// Mitsubishi GX Works2 project: Vol2_R_Cutter_PLC   PLC: Q06UDEH

PROGRAM MAIN
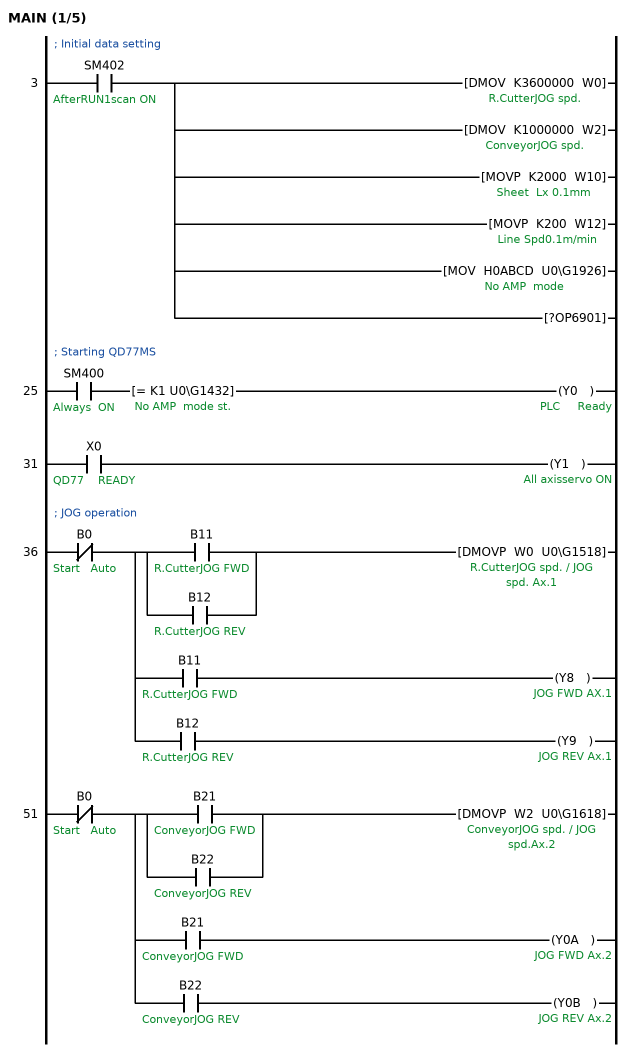
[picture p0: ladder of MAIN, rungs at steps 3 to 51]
; 
; Initial data setting
; 
3     LD      SM402  ; AfterRUN1scan ON
      DMOV    K3600000 W0  ; R.CutterJOG spd.
        [note] JOG speed set : x0.001deg/min
      DMOV    K1000000 W2  ; ConveyorJOG spd.
        [note] JOG speed set : x0.01mm/min
      MOVP    K2000 W10  ; Sheet  Lx 0.1mm
        [note] Production setting
      MOVP    K200 W12  ; Line Spd0.1m/min
      MOV     H0ABCD U0\G1926  ; No AMP  mode
      ?OP6901
; 
; Starting QD77MS
; 
25    LD      SM400  ; Always  ON
      AND=    K1 U0\G1432  ; No AMP  mode st.
      OUT     Y0  ; PLC     Ready
31    LD      X0  ; QD77    READY
      OUT     Y1  ; All axisservo ON
; 
; JOG operation
; 
36    LDI     B0  ; Start   Auto
      MPS
      LD      B11  ; R.CutterJOG FWD
      OR      B12  ; R.CutterJOG REV
      ANB
      DMOVP   W0 U0\G1518  ; JOG spd. Ax.1
      MRD
      AND     B11  ; R.CutterJOG FWD
      OUT     Y8  ; JOG FWD AX.1
      MPP
      AND     B12  ; R.CutterJOG REV
      OUT     Y9  ; JOG REV Ax.1
51    LDI     B0  ; Start   Auto
      MPS
      LD      B21  ; ConveyorJOG FWD
      OR      B22  ; ConveyorJOG REV
      ANB
      DMOVP   W2 U0\G1618  ; JOG spd.Ax.2
      MRD
      AND     B21  ; ConveyorJOG FWD
      OUT     Y0A  ; JOG FWD Ax.2
      MPP
      AND     B22  ; ConveyorJOG REV
      OUT     Y0B  ; JOG REV Ax.2
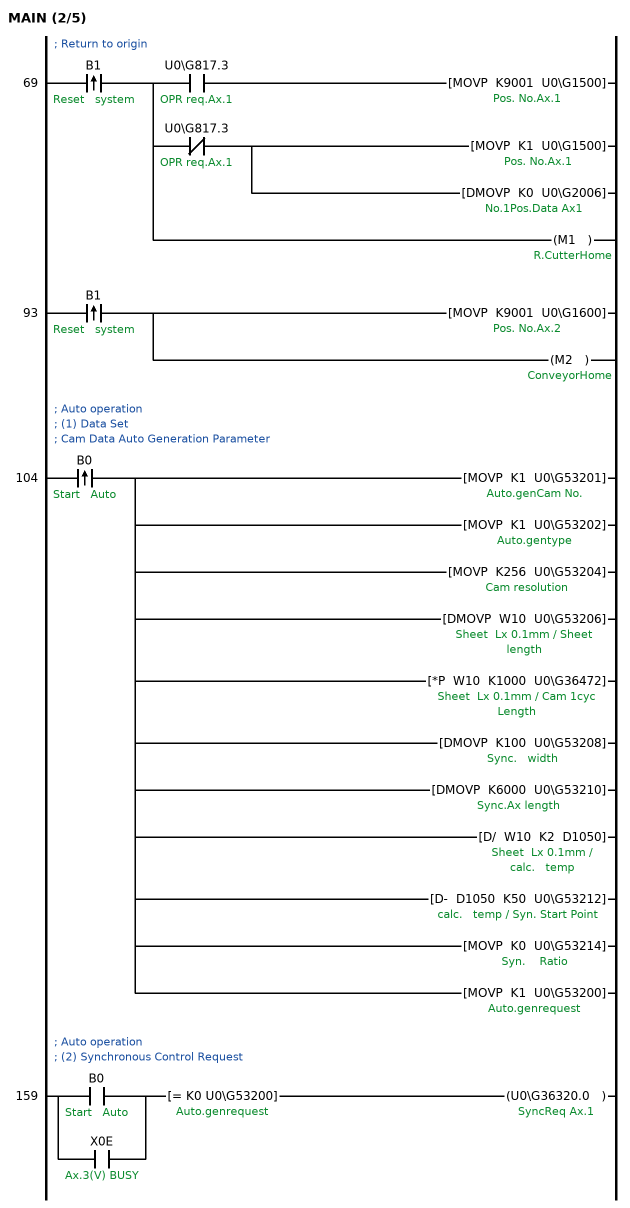
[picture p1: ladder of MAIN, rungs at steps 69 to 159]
; 
; Return to origin
; 
69    LDP     B1  ; Reset   system
      MPS
      AND     U0\G817.3  ; OPR req.Ax.1
      MOVP    K9001 U0\G1500  ; Pos. No.Ax.1
      MRD
      ANI     U0\G817.3  ; OPR req.Ax.1
      MOVP    K1 U0\G1500
      DMOVP   K0 U0\G2006  ; No.1Pos.Data Ax1
      MPP
      OUT     M1  ; R.CutterHome
93    LDP     B1  ; Reset   system
      MOVP    K9001 U0\G1600  ; Pos. No.Ax.2
      OUT     M2  ; ConveyorHome
; 
; Auto operation
; (1) Data Set
; Cam Data Auto Generation Parameter
; 
104   LDP     B0  ; Start   Auto
      MOVP    K1 U0\G53201  ; Auto.genCam No.
        [note] Cam auto-generation parameter.
      MOVP    K1 U0\G53202  ; Auto.gentype
      MOVP    K256 U0\G53204  ; Cam resolution
      DMOVP   W10 U0\G53206  ; Sheet   length
      *P      W10 K1000 U0\G36472  ; Cam 1cyc Length
      DMOVP   K100 U0\G53208  ; Sync.   width
      DMOVP   K6000 U0\G53210  ; Sync.Ax length
      D/      W10 K2 D1050  ; calc.   temp
      D-      D1050 K50 U0\G53212  ; Syn. Start Point
      MOVP    K0 U0\G53214  ; Syn.    Ratio
      MOVP    K1 U0\G53200  ; Auto.genrequest
; 
; Auto operation
; (2) Synchronous Control Request
; 
159   LD      B0  ; Start   Auto
      OR      X0E  ; Ax.3(V) BUSY
      AND=    K0 U0\G53200  ; Auto.genrequest
      OUT     U0\G36320.0  ; SyncReq Ax.1
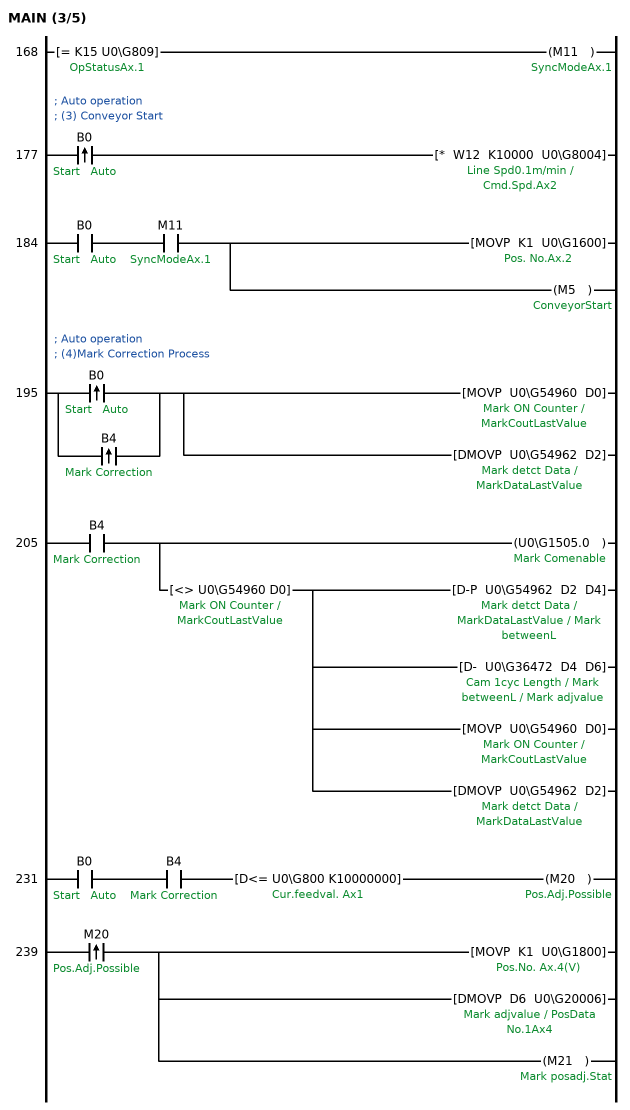
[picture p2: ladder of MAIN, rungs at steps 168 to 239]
168   LD=     K15 U0\G809  ; OpStatusAx.1
      OUT     M11  ; SyncModeAx.1
; 
; Auto operation
; (3) Conveyor Start
; 
177   LDP     B0  ; Start   Auto
      *       W12 K10000 U0\G8004  ; Cmd.Spd.Ax2
        [note] Conveyor Speed Set
184   LD      B0  ; Start   Auto
      AND     M11  ; SyncModeAx.1
      MOVP    K1 U0\G1600
      OUT     M5  ; ConveyorStart
; 
; Auto operation
; (4)Mark Correction Process
; 
195   LDP     B0  ; Start   Auto
      ORP     B4  ; Mark Correction
      MOVP    U0\G54960 D0  ; Mark ON Counter / MarkCoutLastValue
      DMOVP   U0\G54962 D2  ; Mark detct Data / MarkDataLastValue
205   LD      B4  ; Mark Correction
      OUT     U0\G1505.0  ; Mark Comenable
      AND<>   U0\G54960 D0  ; Mark ON Counter / MarkCoutLastValue
      D-P     U0\G54962 D2 D4  ; Mark    betweenL
      D-      U0\G36472 D4 D6  ; Mark adjvalue
      MOVP    U0\G54960 D0
      DMOVP   U0\G54962 D2
231   LD      B0  ; Start   Auto
      AND     B4  ; Mark Correction
      ANDD<=  U0\G800 K10000000  ; Cur.feedval. Ax1
      OUT     M20  ; Pos.Adj.Possible
239   LDP     M20  ; Pos.Adj.Possible
      MOVP    K1 U0\G1800  ; Pos.No. Ax.4(V)
      DMOVP   D6 U0\G20006  ; PosData No.1Ax4
      OUT     M21  ; Mark posadj.Stat
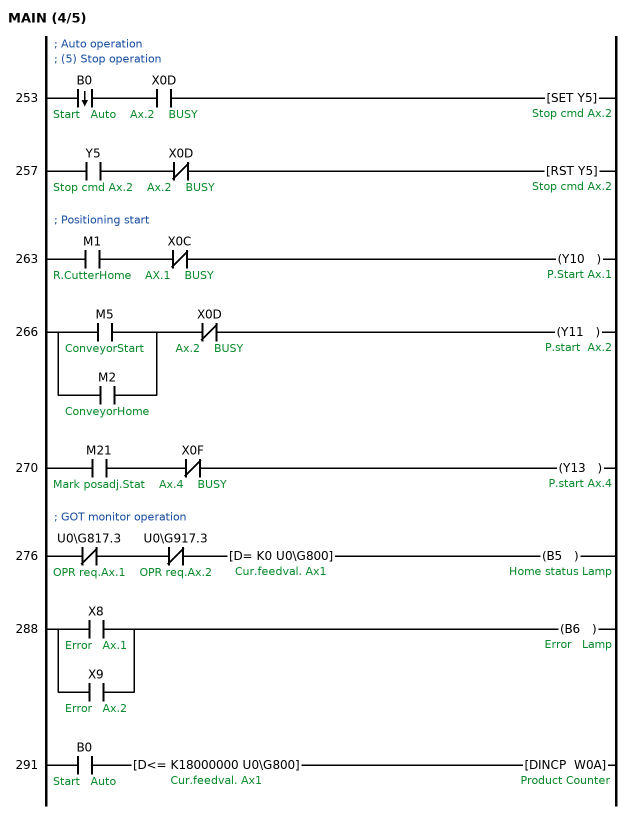
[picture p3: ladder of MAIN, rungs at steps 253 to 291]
; 
; Auto operation
; (5) Stop operation
; 
253   LDF     B0  ; Start   Auto
      AND     X0D  ; Ax.2    BUSY
      SET     Y5  ; Stop cmd Ax.2
        [note] Axes Stop Command
257   LD      Y5  ; Stop cmd Ax.2
      ANI     X0D  ; Ax.2    BUSY
      RST     Y5  ; Stop cmd Ax.2
; 
; Positioning start
; 
263   LD      M1  ; R.CutterHome
      ANI     X0C  ; AX.1    BUSY
      OUT     Y10  ; P.Start Ax.1
266   LD      M5  ; ConveyorStart
      OR      M2  ; ConveyorHome
      ANI     X0D  ; Ax.2    BUSY
      OUT     Y11  ; P.start  Ax.2
270   LD      M21  ; Mark posadj.Stat
      ANI     X0F  ; Ax.4    BUSY
      OUT     Y13  ; P.start Ax.4
; 
; GOT monitor operation
; 
276   LDI     U0\G817.3  ; OPR req.Ax.1
      ANI     U0\G917.3  ; OPR req.Ax.2
      ANDD=   K0 U0\G800  ; Cur.feedval. Ax1
      OUT     B5  ; Home status Lamp
288   LD      X8  ; Error   Ax.1
      OR      X9  ; Error   Ax.2
      OUT     B6  ; Error   Lamp
291   LD      B0  ; Start   Auto
      ANDD<=  K18000000 U0\G800  ; Cur.feedval. Ax1
      DINCP   W0A  ; Product Counter
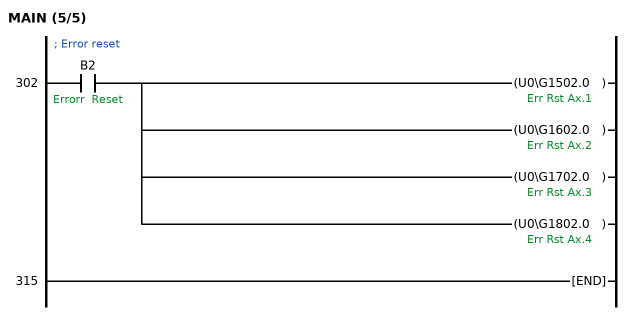
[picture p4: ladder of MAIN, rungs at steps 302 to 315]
; 
; Error reset
; 
302   LD      B2  ; Errorr  Reset
      OUT     U0\G1502.0  ; Err Rst Ax.1
      OUT     U0\G1602.0  ; Err Rst Ax.2
      OUT     U0\G1702.0  ; Err Rst Ax.3
      OUT     U0\G1802.0  ; Err Rst Ax.4
315   END
END_PROGRAM

PROGRAM Mark_Sim
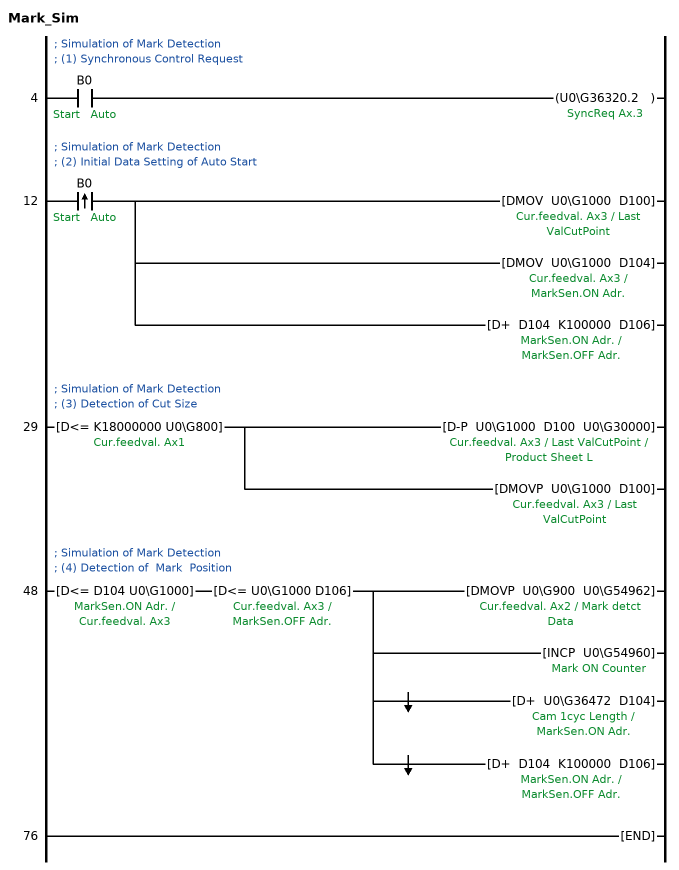
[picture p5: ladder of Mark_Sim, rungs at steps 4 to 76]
; 
; Simulation of Mark Detection
; (1) Synchronous Control Request
; 
4     LD      B0  ; Start   Auto
      OUT     U0\G36320.2  ; SyncReq Ax.3
; 
; Simulation of Mark Detection
; (2) Initial Data Setting of Auto Start
; 
12    LDP     B0  ; Start   Auto
      DMOV    U0\G1000 D100  ; Cur.feedval. Ax3 / Last ValCutPoint
      DMOV    U0\G1000 D104  ; MarkSen.ON Adr.
      D+      D104 K100000 D106  ; MarkSen.OFF Adr.
; 
; Simulation of Mark Detection
; (3) Detection of Cut Size
; 
29    LDD<=   K18000000 U0\G800  ; Cur.feedval. Ax1
      D-P     U0\G1000 D100 U0\G30000  ; Product Sheet L
      DMOVP   U0\G1000 D100
; 
; Simulation of Mark Detection
; (4) Detection of  Mark  Position
; 
48    LDD<=   D104 U0\G1000  ; MarkSen.ON Adr. / Cur.feedval. Ax3
      ANDD<=  U0\G1000 D106  ; Cur.feedval. Ax3 / MarkSen.OFF Adr.
      DMOVP   U0\G900 U0\G54962  ; Cur.feedval. Ax2 / Mark detct Data
      INCP    U0\G54960  ; Mark ON Counter
      MPS
      MEF
      D+      U0\G36472 D104  ; Cam 1cyc Length
      MPP
      MEF
      D+      D104 K100000 D106
76    END
END_PROGRAM

// device comments not shown above
Y6  ; Stop cmdAx.3(V)
Y12  ; P.start Ax.3(V)
Y14  ; P.start Ax.5
Y15  ; Axis 6Positioning start
Y16  ; Axis 7Positioning start
Y17  ; Axis 8Positioning start
Y18  ; P.start Ax.9(V)
Y19  ; P.start Ax.10(V)
Y1A  ; Axis11Positioning start
Y1B  ; Axis12Positioning start
Y1C  ; Axis13Positioning start
Y1D  ; Axis14Positioning start
Y1E  ; Axis15Positioning start
Y1F  ; Axis16Positioning start
Y20  ; Mark ON
X1  ; Synchronization flag
X10  ; Axis 1  BUSY
X11  ; Axis 2  BUSY
X12  ; Axis 3  BUSY
X13  ; Axis 4  BUSY
X14  ; Axis 5  BUSY
X15  ; Axis 6  BUSY
X16  ; Axis 7  BUSY
X17  ; Axis 8  BUSY
X18  ; Axis 9  BUSY
X19  ; Axis 10 BUSY
X1A  ; Axis 11 BUSY
X1B  ; Axis 12 BUSY
X1C  ; Axis 13 BUSY
X1D  ; Axis 14 BUSY
X1E  ; Axis 15 BUSY
X1F  ; Axis 16 BUSY
M0  ; Auto opeStart
M3  ; V.Roll_2 Home
M4  ; Sealer  Home
M12  ; SyncModeAx.2
M13  ; SyncModeAx.3
M14  ; SyncReq JOG Ax1
M15  ; Sy.Req JOG Ax2,3
M19  ; V.RollerStart
M22  ; Sealer  FWD
M23  ; Sealing
M24  ; Seal/CutHomePos
M30  ; V.Rollercomp.
M31  ; Sealer  FWD pos.
M32  ; Sealer  REV pos.
M100  ; Sheet   Cutting
B3  ; Forced  Stop
B41  ; Sealer  JOG FWD
B42  ; Sealer  JOG REV
B51  ; ConveyorJOG FWD
B52  ; ConveyorJOG REV
T0  ; Sealing Timer
W4  ; Sealer  JOG spd.
W6  ; ConveyorJOG spd.
W14  ; Seal stroke mm
W16  ; Sealing time ms
W20  ; Roll DIAmm
W24  ; Monitor pos. Ax2
W28  ; Monitor pos. Ax3
W2C  ; Monitor pos.Ax4
W30  ; Monitor spd. Ax5
D108  ; LastTimeMarkData
D1000  ; Cycle   time ms
D1002  ; Seal travel time
D1004  ; Cam 1cycTime ms
D1006  ; Cam 1cycspd.
